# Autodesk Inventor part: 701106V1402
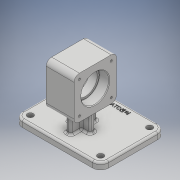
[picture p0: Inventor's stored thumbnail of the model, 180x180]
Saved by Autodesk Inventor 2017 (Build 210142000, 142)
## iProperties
Part Number: 701106V1402
Material: 일반
Document SubType Name: Modeling
Designer: 222
Density: 1 g/cm^3
Appearance: 기본값
Mass: 253.042 g
Surface Area: 542.794 cm^2
Volume: 253.042 cm^3
Author: 222
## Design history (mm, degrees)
sketch "스케치1"
  geometry: L1 (32, -32)-(-32, -32); L2 (-32, -32)-(-32, 32); L3 (-32, 32)-(32, 32); L4 (32, 32)-(32, -32); L5 (32, -32)-(-32, 32); L6 (-32, -32)-(32, 32); 1 further point
  constraints: 12 end point, 2 midpoint, 2 parallel, 1 horizontal, 1 perpendicular
  dimensions: "d0" = 64 distance of L2.end L3.end; "d1" = 64 distance of L1.end L2.end
extrude "돌출1" new body sketch "스케치1" stored distance "d2" = 42; taper "d3" = 0 deg
fillet "모깎기1" dims "d4" = 8
sketch "스케치3" dims "d19" = 42
  geometry: A1 r 8 centre (-24, -24) between (-32, -24) and (-24, -32) reference; A2 r 8 centre (24, -24) between (24, -32) and (32, -24) reference; 3 further points
  constraints: 2 coincident
hole "구멍1" sketch "스케치3" at (-24, -24), (24, -24) diameter "d9" = 3.242; stored, may be unused: countersink angle "d13" = 90 deg, drill point angle "d15" = 118 deg; dims "d10" = 8, "d11" = 4, "d12" = 2, "d14" = 10
sketch "스케치4"
  geometry: C1 r 18 at (0, 0); 1 further point
  constraints: 1 centre point, 1 coincident
  dimensions: "d16" = 36 diameter of C1
extrude "돌출2" cut sketch "스케치4" distance "d17" = 74; taper "d18" = 0 deg
sketch "스케치5"
  geometry: C1 r 21 at (0, 0); 1 further point
  constraints: 1 centre point, 1 coincident
  dimensions: "d19" = 42 diameter of C1
extrude "돌출3" cut sketch "스케치5" distance "d20" = 15; taper "d21" = 0 deg
node "작업 평면2"
sketch "스케치8"
  geometry: L1 (65, -60)-(-65, -60); L2 (-65, -60)-(-65, -70); L3 (-65, -70)-(65, -70); L4 (65, -70)-(65, -60); 2 further points
  constraints: 8 end point, 2 parallel, 1 horizontal, 1 midpoint, 1 perpendicular, 1 vertical alignment
  dimensions: "d27" = 130 distance of L3.end L2.end; "d28" = 10 distance of L2.end L1.end; "d29" = 70 distance from line of L3 point (0, 0)
extrude "돌출4" join sketch "스케치8" distance "d30" = 98; taper "d31" = 0 deg
fillet "모깎기2" dims "d32" = 12
hole "구멍2" diameter "d35" = 9; stored, may be unused: countersink angle "d39" = 90 deg, drill point angle "d41" = 0 deg; dims "d36" = 6, "d37" = 4, "d38" = 2, "d40" = 25, "d66" = 10, "d67" = 10
sketch "스케치9"
  geometry: L1 (17, -32)-(-17, -32); L2 (-17, -32)-(-17, -60); L3 (-17, -60)-(17, -60); L4 (17, -60)-(17, -32); L5 (53, -60)-(-53, -60) reference; L6 (-21, -32)-(21, -32) reference; 3 further points
  constraints: 8 end point, 4 midpoint, 2 parallel, 1 horizontal, 1 perpendicular
  dimensions: "d46" = 34 distance of L3.end L2.end
extrude "돌출5" join sketch "스케치9" stored distance "d48" = 8; taper "d49" = 0 deg
sketch "스케치10"
  geometry: L1 (-11.381, -34.824)-(-12.063, -34.824); L2 (-20, -32)-(20, -32); L3 (20, -32)-(20, -60); L4 (20, -60)-(-20, -60); L5 (-20, -60)-(-20, -32); L6 (4, -32)-(-4, -32) reference; L7 (-4, -60)-(4, -60) reference; 3 further points
  constraints: 10 end point, 4 midpoint, 2 horizontal, 2 parallel, 1 perpendicular
  dimensions: "d50" = 40 distance of L3.end L4.end
extrude "돌출6" join sketch "스케치10" stored distance "d52" = 8; taper "d53" = 0 deg
chamfer "모따기1" distance "d54" = 1; stored, may be unused: second distance "d55" = 2, angle "d56" = 45 deg
fillet "모깎기3" dims "d57" = 0.3
fillet "모깎기4" dims "d58" = 3
fillet "모깎기5" dims "d59" = 3
fillet "모깎기6" dims "d60" = 3
sketch "스케치11"
  geometry: L1 (19.376, 86.962)-(86.624, 86.962); L2 (86.624, 86.962)-(86.624, 83.038); L3 (86.624, 83.038)-(19.376, 83.038); L4 (19.376, 83.038)-(19.376, 86.962); L5 (53, 86.962)-(53, 83.038); L6 (19.376, 85)-(86.624, 85); L7 (118, 9)-(118, 83) reference; L8 (106, 95)-(0, 95) reference; 1 further point
  constraints: 4 end point, 4 midpoint, 2 other
  dimensions: "d61" = 65 distance from line of L7 L5.start; "d63" = 10 distance between parallel lines of L8 L6
extrude "돌출7" join sketch "스케치11" distance "d64" = 0.5; taper "d65" = 0 deg
sketch "스케치12"
  geometry: 1 further point
node "솔리드1"
mirror "미러1"
mirror "미러2"
mirror "미러3"
pattern_linear "직사각형 패턴1"
other parameters: "d26" = 62
